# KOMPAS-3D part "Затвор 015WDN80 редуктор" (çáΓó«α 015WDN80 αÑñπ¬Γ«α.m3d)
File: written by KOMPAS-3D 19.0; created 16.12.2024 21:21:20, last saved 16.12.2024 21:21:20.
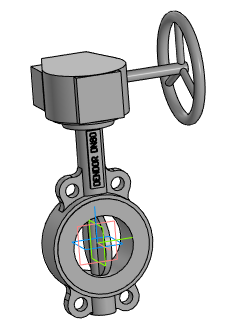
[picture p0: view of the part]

Document properties: Автор: Евгений; Полное имя файла: ..\Затвор 015WDN80 редуктор.a3d

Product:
- Part/product: Затвор 015WDN80 редуктор
    Масса: 11.3292

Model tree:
1. Операция без истории:1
